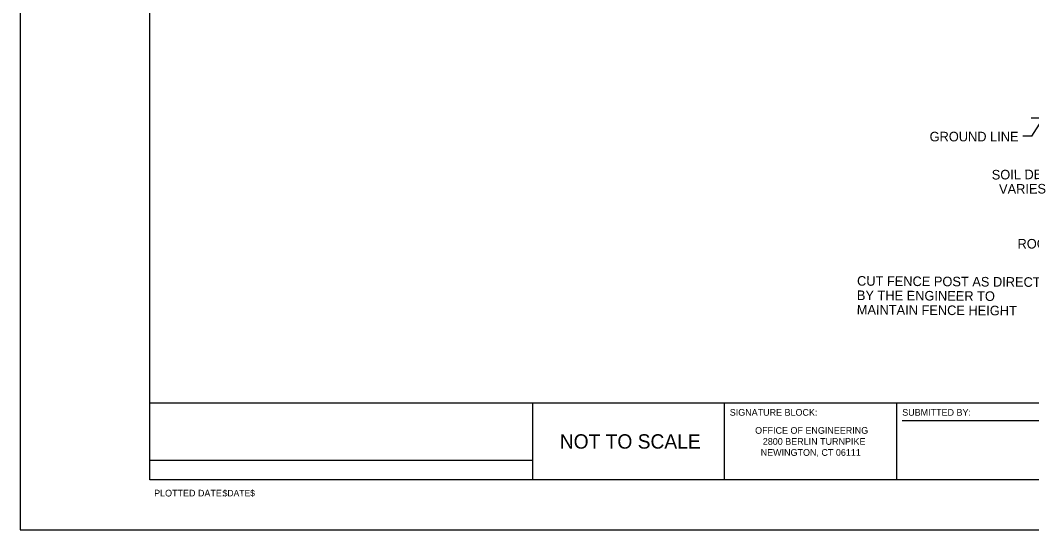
# Model space of a CAD drawing. Extents: x 0 to 2.85, y -0.1 to 1.83.
# Drawn here: x 0 to 1.056, y 0 to 0.531 of the extents above; entities that cross this region are included whole.
import ezdxf

# ---------------------------------------------------------------- set-up
doc = ezdxf.new("R2010")
doc.units = 0
for name, color, linetype in [('BDR_Inner_Perimeter', 7, 'Continuous'), ('BDR_Outer_Perimeter', 7, 'Continuous'), ('BDR_Title_Block', 7, 'Continuous'), ('CT_Dimensions', 7, 'Continuous'), ('sb_Earth', 7, 'Continuous')]:
    doc.layers.add(name, color=color, linetype=linetype)

msp = doc.modelspace()

# ---------------------------------------------------------------- linework, layer by layer
at = {"layer": 'BDR_Inner_Perimeter'}
msp.add_lwpolyline([(0.1354, 1.7812), (2.7812, 1.7812), (2.7812, 0.0521), (0.1354, 0.0521)], close=True, dxfattribs=at)
at = {"layer": 'BDR_Outer_Perimeter'}
msp.add_lwpolyline([(0, 0), (2.8333, 0), (2.8333, 1.8333), (0, 1.8333)], close=True, dxfattribs=at)
at = {"layer": 'BDR_Title_Block'}
for p, q in [((2.7812, 0.1321), (0.1354, 0.1321)), ((0.5354, 0.0521), (0.5354, 0.1321)), ((0.7354, 0.0521), (0.7354, 0.1321)), ((0.9154, 0.0521), (0.9154, 0.1321)), ((0.921, 0.114), (1.071, 0.114)), ((0.5354, 0.0721), (0.1354, 0.0721))]:
    msp.add_line(p, q, dxfattribs=at)
at = {"layer": 'CT_Dimensions'}
for q in [(1.0669, 0.4269), (1.047, 0.4106)]:
    msp.add_line((1.0562, 0.4106), q, dxfattribs=at)
at = {"layer": 'sb_Earth'}
msp.add_line((1.2488, 0.4292), (1.0556, 0.4293), dxfattribs=at)

# ---------------------------------------------------------------- texts
at = {"layer": 'BDR_Title_Block'}
for s, height, p in [('SIGNATURE BLOCK:  ', 0.007, (0.7409, 0.1189)), ('SUBMITTED BY:', 0.007, (0.921, 0.1189)), ('OFFICE OF ENGINEERING', 0.007, (0.7674, 0.1001)), ('NOT TO SCALE', 0.015, (0.5634, 0.0846)), ('2800 BERLIN TURNPIKE', 0.007, (0.7754, 0.0886)), ('NEWINGTON, CT 06111', 0.007, (0.7732, 0.0771)), ('PLOTTED DATE:', 0.007, (0.1398, 0.0347))]:
    msp.add_text(s, height=height, dxfattribs=at).set_placement(p)
msp.add_text('$DATE$', height=0.00667, rotation=0.125, dxfattribs=at).set_placement((0.2114, 0.0348))
at = {"layer": 'CT_Dimensions'}
msp.add_text('GROUND LINE', height=0.01, dxfattribs=at).set_placement((0.9496, 0.4051))
for s, rotation, p in [('SOIL DEPTH', 0.4595, (1.0145, 0.3653)), ('  VARIES', 0.4595, (1.0147, 0.3503)), ('ROCK DEPTH', 0.0158, (1.0414, 0.2933)), ('CUT FENCE POST AS DIRECTED', 359.6101, (0.8738, 0.2546)), ('BY THE ENGINEER TO', 359.6101, (0.8736, 0.2396)), ('MAINTAIN FENCE HEIGHT', 359.6101, (0.8735, 0.2246))]:
    msp.add_text(s, height=0.01, rotation=rotation, dxfattribs=at).set_placement(p)

doc.saveas('drawing.dxf')
